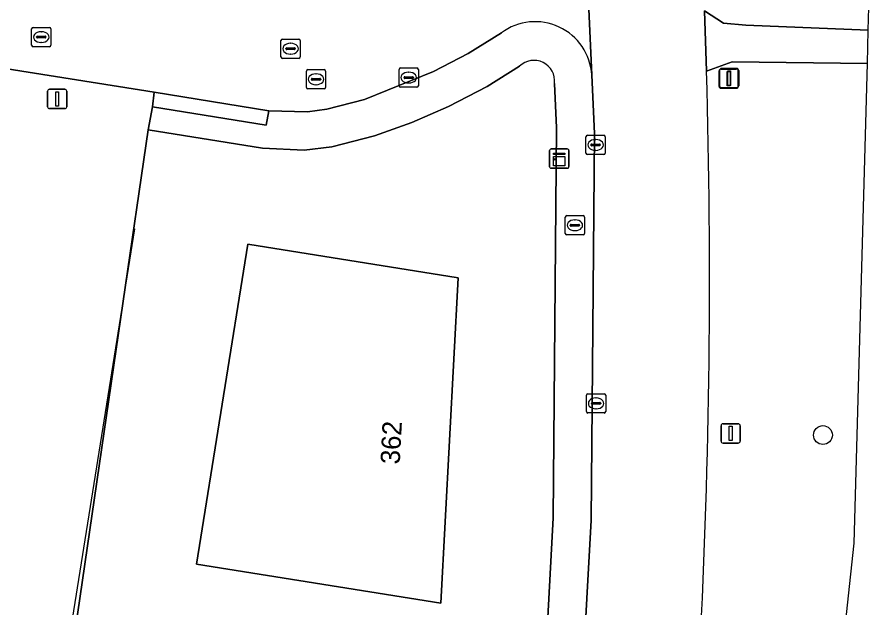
# Model space of a CAD drawing. Extents: x 154324 to 155744, y 382937 to 384188.
# Drawn here: x 155353.31 to 155397.49, y 383349.73 to 383380.36 of the extents above; entities that cross this region are included whole.
import ezdxf

# ---------------------------------------------------------------- set-up
doc = ezdxf.new("R2010")
doc.units = 0
for name, color, linetype in [('IMGEO_Berm_groen', 7, 'Continuous'), ('IMGEO_Boom', 7, 'Continuous'), ('IMGEO_Brandkraan', 7, 'Continuous'), ('IMGEO_Erf', 7, 'Continuous'), ('IMGEO_Groenvoorziening', 7, 'Continuous'), ('IMGEO_Hek', 7, 'Continuous'), ('IMGEO_Kast', 7, 'Continuous'), ('IMGEO_Kolk', 7, 'Continuous'), ('IMGEO_Lichtmast', 7, 'Continuous'), ('IMGEO_Pand', 7, 'Continuous'), ('IMGEO_Pand_nummerreeks', 7, 'Continuous'), ('IMGEO_Rijbaan_lokaal_gesloten', 7, 'Continuous'), ('IMGEO_Rijbaan_lokaal_open', 7, 'Continuous'), ('IMGEO_Rioolput', 7, 'Continuous'), ('IMGEO_Voetpad_halfverhard', 7, 'Continuous'), ('IMGEO_Voetpad_open', 7, 'Continuous')]:
    doc.layers.add(name, color=color, linetype=linetype)

msp = doc.modelspace()

# ---------------------------------------------------------------- linework, layer by layer
at = {"layer": 'IMGEO_Berm_groen'}
for points in [[(155388.962, 383380.68), (155389.952, 383380.04), (155391.104, 383379.937), (155397.46, 383379.674), (155397.493, 383380.862), (155397.072, 383397.736)], [(155393.141, 383320.278), (155393.828, 383326.071), (155396.722, 383353.081), (155397.412, 383377.951), (155390.399, 383378.047), (155389.068, 383377.555)]]:
    msp.add_lwpolyline(points, dxfattribs=at)
msp.add_arc((155026.251, 383366.771), 362.977, 356.94684, 1.70249, dxfattribs=at)
at = {"layer": 'IMGEO_Boom'}
msp.add_circle((155395.106, 383358.693), 0.489, dxfattribs=at)
at = {"layer": 'IMGEO_Brandkraan'}
for p, q in [((155381.741, 383369.142), (155381.741, 383369.994)), ((155381.816, 383370.068), (155382.668, 383370.068)), ((155382.229, 383369.848), (155382.254, 383369.848)), ((155382.742, 383369.994), (155382.742, 383369.142)), ((155382, 383369.562), (155382, 383369.574)), ((155382.438, 383369.525), (155382.04, 383369.525)), ((155382.043, 383369.611), (155382.441, 383369.611)), ((155382.484, 383369.574), (155382.484, 383369.562)), ((155382.668, 383369.068), (155381.816, 383369.068)), ((155382.252, 383369.288), (155382.227, 383369.288))]:
    msp.add_line(p, q, dxfattribs=at)
for points in [[(155381.741, 383369.142), (155381.741, 383369.994)], [(155381.816, 383370.068), (155382.668, 383370.068)], [(155382.742, 383369.994), (155382.742, 383369.142)], [(155382.668, 383369.068), (155381.816, 383369.068)]]:
    msp.add_lwpolyline(points, dxfattribs=at)
for centre, radius, start, end in [((155381.818, 383369.992), 0.0765, 91.552, 178.448), ((155381.818, 383369.992), 0.0765, 91.552, 178.448), ((155382.666, 383369.992), 0.0765, 1.552, 88.448), ((155382.666, 383369.992), 0.0765, 1.552, 88.448), ((155382.04, 383369.571), 0.0403, 85.8775, 175.7526), ((155382.037, 383369.561), 0.0366, 178.938, 274.7102), ((155382.441, 383369.568), 0.043, 264.8664, 352.4533), ((155382.445, 383369.573), 0.0386, 1.7309, 96.639), ((155381.818, 383369.144), 0.0765, 181.552, 268.448), ((155381.818, 383369.144), 0.0765, 181.552, 268.448), ((155382.666, 383369.144), 0.0765, 271.552, 358.448), ((155382.666, 383369.144), 0.0765, 271.552, 358.448)]:
    msp.add_arc(centre, radius, start, end, dxfattribs=at)
for centre, major_axis, ratio, start_param, end_param in [((155382.228, 383369.568), (-0.387, 0.002), 0.722429, 4.712389, 7.853982), ((155382.253, 383369.568), (-0.39, 0.002), 0.717154, 1.570796, 4.712389)]:
    msp.add_ellipse(centre, major_axis=major_axis, ratio=ratio, start_param=start_param, end_param=end_param, dxfattribs=at)
at = {"layer": 'IMGEO_Erf'}
for points in [[(155379.37, 383377.808), (155377.693, 383376.769), (155375.684, 383375.726), (155373.779, 383374.896), (155371.854, 383374.2), (155369.627, 383373.633), (155368.206, 383373.461), (155366.044, 383373.562), (155360.106, 383374.508), (155358.814, 383365.632), (155354.844, 383338.369), (155354.723, 383337.539), (155380.034, 383334.398), (155381.119, 383354.403)], [(155381.119, 383354.403), (155381.295, 383374.612), (155381.184, 383376.925)]]:
    msp.add_lwpolyline(points, dxfattribs=at)
msp.add_lwpolyline([(155362.62, 383351.999), (155365.283, 383368.59), (155376.195, 383366.839), (155375.291, 383349.97)], close=True, dxfattribs=at)
msp.add_arc((155380.121, 383377.046), 1.07, 353.5115, 134.5776, dxfattribs=at)
at = {"layer": 'IMGEO_Groenvoorziening'}
for points in [[(155358.814, 383365.632), (155360.106, 383374.508), (155360.327, 383375.705), (155360.426, 383376.464), (155295.925, 383386.713), (155295.512, 383384.113), (155295.052, 383381.177), (155292.112, 383381.637), (155292.571, 383384.573), (155292.985, 383387.18), (155280.782, 383389.119), (155238.742, 383395.799)], [(155381.974, 383334.287), (155380.034, 383334.398), (155354.723, 383337.539), (155354.844, 383338.369), (155358.814, 383365.632)]]:
    msp.add_lwpolyline(points, dxfattribs=at)
at = {"layer": 'IMGEO_Hek'}
msp.add_lwpolyline([(155369.884, 383336.037), (155354.478, 383338.426), (155359.411, 383369.381)], dxfattribs=at)
at = {"layer": 'IMGEO_Kast'}
for p, q in [((155380.931, 383372.598), (155380.931, 383373.439)), ((155380.931, 383373.439), (155380.931, 383372.598)), ((155381.006, 383373.523), (155381.847, 383373.523)), ((155381.847, 383373.523), (155381.006, 383373.523)), ((155381.931, 383373.448), (155381.931, 383372.607)), ((155381.931, 383372.607), (155381.931, 383373.448)), ((155381.856, 383372.523), (155381.015, 383372.523)), ((155381.015, 383372.523), (155381.856, 383372.523))]:
    msp.add_line(p, q, dxfattribs=at)
for points in [[(155381.126, 383373.313), (155381.726, 383373.313), (155381.726, 383373.228), (155381.126, 383373.228), (155381.126, 383373.313)], [(155381.126, 383373.138), (155381.726, 383373.138), (155381.726, 383372.649), (155381.126, 383372.649), (155381.126, 383373.138)]]:
    msp.add_lwpolyline(points, dxfattribs=at)
msp.add_circle((155381.21, 383372.987), 0.0377, dxfattribs=at)
for centre, start, end in [((155381.009, 383373.445), 92.4484, 184.2845), ((155381.009, 383373.445), 92.4484, 184.2845), ((155381.853, 383373.445), 2.4484, 94.2845), ((155381.853, 383373.445), 2.4484, 94.2845), ((155381.009, 383372.601), 182.4484, 274.2845), ((155381.009, 383372.601), 182.4484, 274.2845), ((155381.853, 383372.601), 272.4484, 4.2845), ((155381.853, 383372.601), 272.4484, 4.2845)]:
    msp.add_arc(centre, 0.0779, start, end, dxfattribs=at)
at = {"layer": 'IMGEO_Kolk'}
for p, q in [((155373.12, 383376.797), (155373.12, 383377.649)), ((155373.195, 383377.723), (155374.047, 383377.723)), ((155373.608, 383377.503), (155373.633, 383377.503)), ((155374.121, 383377.649), (155374.121, 383376.797)), ((155373.379, 383377.217), (155373.379, 383377.229)), ((155373.817, 383377.18), (155373.419, 383377.18)), ((155373.422, 383377.266), (155373.82, 383377.266)), ((155373.631, 383376.943), (155373.606, 383376.943)), ((155373.863, 383377.229), (155373.863, 383377.217)), ((155374.047, 383376.723), (155373.195, 383376.723)), ((155382.815, 383373.305), (155382.815, 383374.157)), ((155382.89, 383374.231), (155383.742, 383374.231)), ((155383.303, 383374.011), (155383.328, 383374.011)), ((155383.816, 383374.157), (155383.816, 383373.305)), ((155383.074, 383373.725), (155383.074, 383373.737)), ((155383.512, 383373.688), (155383.114, 383373.688)), ((155383.117, 383373.774), (155383.515, 383373.774)), ((155383.326, 383373.451), (155383.301, 383373.451)), ((155383.558, 383373.737), (155383.558, 383373.725)), ((155383.742, 383373.231), (155382.89, 383373.231)), ((155382.838, 383359.91), (155382.838, 383360.762)), ((155382.913, 383360.836), (155383.765, 383360.836)), ((155383.326, 383360.616), (155383.351, 383360.616)), ((155383.839, 383360.762), (155383.839, 383359.91)), ((155383.097, 383360.33), (155383.097, 383360.342)), ((155383.535, 383360.293), (155383.137, 383360.293)), ((155383.14, 383360.379), (155383.538, 383360.379)), ((155383.581, 383360.342), (155383.581, 383360.33)), ((155383.765, 383359.836), (155382.913, 383359.836)), ((155383.349, 383360.056), (155383.324, 383360.056))]:
    msp.add_line(p, q, dxfattribs=at)
for points in [[(155373.12, 383376.797), (155373.12, 383377.649)], [(155373.195, 383377.723), (155374.047, 383377.723)], [(155374.121, 383377.649), (155374.121, 383376.797)], [(155374.047, 383376.723), (155373.195, 383376.723)], [(155382.815, 383373.305), (155382.815, 383374.157)], [(155382.89, 383374.231), (155383.742, 383374.231)], [(155383.816, 383374.157), (155383.816, 383373.305)], [(155383.742, 383373.231), (155382.89, 383373.231)], [(155382.838, 383359.91), (155382.838, 383360.762)], [(155382.913, 383360.836), (155383.765, 383360.836)], [(155383.839, 383360.762), (155383.839, 383359.91)], [(155383.765, 383359.836), (155382.913, 383359.836)]]:
    msp.add_lwpolyline(points, dxfattribs=at)
for centre, radius, start, end in [((155373.197, 383377.647), 0.0765, 91.552, 178.448), ((155373.197, 383377.647), 0.0765, 91.552, 178.448), ((155374.045, 383377.647), 0.0765, 1.552, 88.448), ((155374.045, 383377.647), 0.0765, 1.552, 88.448), ((155373.419, 383377.226), 0.0403, 85.8775, 175.7526), ((155373.416, 383377.216), 0.0366, 178.938, 274.7102), ((155373.82, 383377.223), 0.043, 264.8664, 352.4533), ((155373.824, 383377.228), 0.0386, 1.7309, 96.639), ((155373.197, 383376.799), 0.0765, 181.552, 268.448), ((155373.197, 383376.799), 0.0765, 181.552, 268.448), ((155374.045, 383376.799), 0.0765, 271.552, 358.448), ((155374.045, 383376.799), 0.0765, 271.552, 358.448), ((155382.892, 383374.155), 0.0765, 91.552, 178.448), ((155382.892, 383374.155), 0.0765, 91.552, 178.448), ((155383.74, 383374.155), 0.0765, 1.552, 88.448), ((155383.74, 383374.155), 0.0765, 1.552, 88.448), ((155383.114, 383373.734), 0.0403, 85.8775, 175.7526), ((155383.111, 383373.724), 0.0366, 178.938, 274.7102), ((155383.515, 383373.731), 0.043, 264.8664, 352.4533), ((155383.519, 383373.736), 0.0386, 1.7309, 96.639), ((155382.892, 383373.307), 0.0765, 181.552, 268.448), ((155382.892, 383373.307), 0.0765, 181.552, 268.448), ((155383.74, 383373.307), 0.0765, 271.552, 358.448), ((155383.74, 383373.307), 0.0765, 271.552, 358.448), ((155382.915, 383360.76), 0.0765, 91.552, 178.448), ((155382.915, 383360.76), 0.0765, 91.552, 178.448), ((155383.763, 383360.76), 0.0765, 1.552, 88.448), ((155383.763, 383360.76), 0.0765, 1.552, 88.448), ((155383.137, 383360.339), 0.0403, 85.8775, 175.7526), ((155383.134, 383360.329), 0.0366, 178.938, 274.7102), ((155383.538, 383360.336), 0.043, 264.8664, 352.4533), ((155383.542, 383360.341), 0.0386, 1.7309, 96.639), ((155382.915, 383359.912), 0.0765, 181.552, 268.448), ((155382.915, 383359.912), 0.0765, 181.552, 268.448), ((155383.763, 383359.912), 0.0765, 271.552, 358.448), ((155383.763, 383359.912), 0.0765, 271.552, 358.448)]:
    msp.add_arc(centre, radius, start, end, dxfattribs=at)
for centre, major_axis, ratio, start_param, end_param in [((155373.607, 383377.223), (-0.387, 0.002), 0.722429, 4.712389, 7.853982), ((155373.632, 383377.223), (-0.39, 0.002), 0.717154, 1.570796, 4.712389), ((155383.302, 383373.731), (-0.387, 0.002), 0.722429, 4.712389, 7.853982), ((155383.327, 383373.731), (-0.39, 0.002), 0.717154, 1.570796, 4.712389), ((155383.325, 383360.336), (-0.387, 0.002), 0.722429, 4.712389, 7.853982), ((155383.35, 383360.336), (-0.39, 0.002), 0.717154, 1.570796, 4.712389)]:
    msp.add_ellipse(centre, major_axis=major_axis, ratio=ratio, start_param=start_param, end_param=end_param, dxfattribs=at)
at = {"layer": 'IMGEO_Lichtmast'}
for p, q in [((155389.723, 383376.768), (155389.723, 383377.568)), ((155389.723, 383377.568), (155389.723, 383376.768)), ((155389.747, 383376.795), (155389.747, 383377.595)), ((155389.747, 383377.595), (155389.747, 383376.795)), ((155389.823, 383377.668), (155390.613, 383377.668)), ((155390.613, 383377.668), (155389.823, 383377.668)), ((155389.847, 383377.695), (155390.637, 383377.695)), ((155390.637, 383377.695), (155389.847, 383377.695)), ((155390.713, 383377.568), (155390.713, 383376.768)), ((155390.713, 383376.768), (155390.713, 383377.568)), ((155390.737, 383377.595), (155390.737, 383376.795)), ((155390.737, 383376.795), (155390.737, 383377.595)), ((155354.892, 383375.716), (155354.892, 383376.516)), ((155354.892, 383376.516), (155354.892, 383375.716)), ((155354.992, 383376.616), (155355.782, 383376.616)), ((155355.782, 383376.616), (155354.992, 383376.616)), ((155355.882, 383376.516), (155355.882, 383375.716)), ((155355.882, 383375.716), (155355.882, 383376.516)), ((155390.613, 383376.668), (155389.823, 383376.668)), ((155389.823, 383376.668), (155390.613, 383376.668)), ((155390.637, 383376.695), (155389.847, 383376.695)), ((155389.847, 383376.695), (155390.637, 383376.695)), ((155355.782, 383375.616), (155354.992, 383375.616)), ((155354.992, 383375.616), (155355.782, 383375.616)), ((155389.923, 383359.277), (155390.713, 383359.277)), ((155390.713, 383359.277), (155389.923, 383359.277)), ((155389.823, 383358.377), (155389.823, 383359.177)), ((155389.823, 383359.177), (155389.823, 383358.377)), ((155390.813, 383359.177), (155390.813, 383358.377)), ((155390.813, 383358.377), (155390.813, 383359.177)), ((155390.713, 383358.277), (155389.923, 383358.277)), ((155389.923, 383358.277), (155390.713, 383358.277))]:
    msp.add_line(p, q, dxfattribs=at)
for points in [[(155390.143, 383377.543), (155390.293, 383377.543), (155390.293, 383376.793), (155390.143, 383376.793), (155390.143, 383377.543)], [(155390.167, 383377.57), (155390.317, 383377.57), (155390.317, 383376.82), (155390.167, 383376.82), (155390.167, 383377.57)], [(155355.312, 383376.491), (155355.462, 383376.491), (155355.462, 383375.741), (155355.312, 383375.741), (155355.312, 383376.491)], [(155390.243, 383359.152), (155390.393, 383359.152), (155390.393, 383358.402), (155390.243, 383358.402), (155390.243, 383359.152)]]:
    msp.add_lwpolyline(points, dxfattribs=at)
for centre, start, end in [((155389.823, 383377.568), 90, 180), ((155389.823, 383377.568), 90, 180), ((155389.847, 383377.595), 90, 180), ((155389.847, 383377.595), 90, 180), ((155390.613, 383377.568), 0, 90), ((155390.613, 383377.568), 360, 90), ((155390.637, 383377.595), 0, 90), ((155390.637, 383377.595), 360, 90), ((155354.992, 383376.516), 90, 180), ((155354.992, 383376.516), 90, 180), ((155355.782, 383376.516), 0, 90), ((155355.782, 383376.516), 360, 90), ((155389.823, 383376.768), 180, 270), ((155389.823, 383376.768), 180, 270), ((155389.847, 383376.795), 180, 270), ((155389.847, 383376.795), 180, 270), ((155390.613, 383376.768), 270, 0), ((155390.613, 383376.768), 270, 0), ((155390.637, 383376.795), 270, 0), ((155390.637, 383376.795), 270, 0), ((155354.992, 383375.716), 180, 270), ((155354.992, 383375.716), 180, 270), ((155355.782, 383375.716), 270, 0), ((155355.782, 383375.716), 270, 0), ((155389.923, 383359.177), 90, 180), ((155389.923, 383359.177), 90, 180), ((155390.713, 383359.177), 0, 90), ((155390.713, 383359.177), 360, 90), ((155389.923, 383358.377), 180, 270), ((155389.923, 383358.377), 180, 270), ((155390.713, 383358.377), 270, 0), ((155390.713, 383358.377), 270, 0)]:
    msp.add_arc(centre, 0.1, start, end, dxfattribs=at)
at = {"layer": 'IMGEO_Pand'}
msp.add_lwpolyline([(155376.195, 383366.839), (155365.283, 383368.59), (155362.62, 383351.999), (155375.291, 383349.97)], close=True, dxfattribs=at)
at = {"layer": 'IMGEO_Rijbaan_lokaal_gesloten'}
for points in [[(155383.12, 383377.352), (155382.189, 383397.912)], [(155238.742, 383395.799), (155280.782, 383389.119), (155292.985, 383387.18), (155295.925, 383386.713), (155360.426, 383376.464), (155366.366, 383375.502), (155368.377, 383375.447), (155369.374, 383375.593), (155371.331, 383376.087), (155374.899, 383377.537), (155376.703, 383378.478), (155378.429, 383379.542)]]:
    msp.add_lwpolyline(points, dxfattribs=at)
msp.add_arc((155380.182, 383377.178), 2.943, 3.3838, 126.5651, dxfattribs=at)
at = {"layer": 'IMGEO_Rijbaan_lokaal_open'}
for points in [[(155379.61, 383421.518), (155379.69, 383421.052), (155380.297, 383417.532), (155380.555, 383416.035), (155380.615, 383415.683), (155382.189, 383397.912), (155383.12, 383377.352), (155383.264, 383374.318), (155383.19, 383366.215), (155383.081, 383354.275), (155381.974, 383334.287)], [(155389.068, 383377.555), (155388.962, 383380.68)]]:
    msp.add_lwpolyline(points, dxfattribs=at)
msp.add_arc((155026.251, 383366.771), 362.977, 356.94684, 1.70249, dxfattribs=at)
at = {"layer": 'IMGEO_Rioolput'}
for p, q in [((155354.064, 383378.898), (155354.064, 383379.75)), ((155354.139, 383379.824), (155354.991, 383379.824)), ((155354.552, 383379.604), (155354.577, 383379.604)), ((155355.065, 383379.75), (155355.065, 383378.898)), ((155354.323, 383379.318), (155354.323, 383379.33)), ((155354.761, 383379.281), (155354.363, 383379.281)), ((155354.366, 383379.367), (155354.764, 383379.367)), ((155354.807, 383379.33), (155354.807, 383379.318)), ((155366.996, 383378.295), (155366.996, 383379.147)), ((155367.071, 383379.221), (155367.923, 383379.221)), ((155367.997, 383379.147), (155367.997, 383378.295)), ((155354.991, 383378.824), (155354.139, 383378.824)), ((155354.575, 383379.044), (155354.55, 383379.044)), ((155367.255, 383378.715), (155367.255, 383378.727)), ((155367.693, 383378.678), (155367.295, 383378.678)), ((155367.298, 383378.764), (155367.696, 383378.764)), ((155367.484, 383379.001), (155367.509, 383379.001)), ((155367.739, 383378.727), (155367.739, 383378.715)), ((155367.507, 383378.441), (155367.482, 383378.441)), ((155367.923, 383378.221), (155367.071, 383378.221)), ((155368.313, 383376.71), (155368.313, 383377.562)), ((155368.388, 383377.636), (155369.24, 383377.636)), ((155368.801, 383377.416), (155368.826, 383377.416)), ((155369.314, 383377.562), (155369.314, 383376.71)), ((155368.572, 383377.13), (155368.572, 383377.142)), ((155369.01, 383377.093), (155368.612, 383377.093)), ((155368.615, 383377.179), (155369.013, 383377.179)), ((155369.056, 383377.142), (155369.056, 383377.13)), ((155369.24, 383376.636), (155368.388, 383376.636)), ((155368.824, 383376.856), (155368.799, 383376.856))]:
    msp.add_line(p, q, dxfattribs=at)
for points in [[(155354.064, 383378.898), (155354.064, 383379.75)], [(155354.139, 383379.824), (155354.991, 383379.824)], [(155355.065, 383379.75), (155355.065, 383378.898)], [(155366.996, 383378.295), (155366.996, 383379.147)], [(155367.071, 383379.221), (155367.923, 383379.221)], [(155367.997, 383379.147), (155367.997, 383378.295)], [(155354.991, 383378.824), (155354.139, 383378.824)], [(155367.923, 383378.221), (155367.071, 383378.221)], [(155368.313, 383376.71), (155368.313, 383377.562)], [(155368.388, 383377.636), (155369.24, 383377.636)], [(155369.314, 383377.562), (155369.314, 383376.71)], [(155369.24, 383376.636), (155368.388, 383376.636)]]:
    msp.add_lwpolyline(points, dxfattribs=at)
for centre, radius, start, end in [((155354.141, 383379.748), 0.0765, 91.552, 178.448), ((155354.141, 383379.748), 0.0765, 91.552, 178.448), ((155354.989, 383379.748), 0.0765, 1.552, 88.448), ((155354.989, 383379.748), 0.0765, 1.552, 88.448), ((155354.363, 383379.327), 0.0403, 85.8775, 175.7526), ((155354.36, 383379.317), 0.0366, 178.938, 274.7102), ((155354.764, 383379.324), 0.043, 264.8664, 352.4533), ((155354.768, 383379.329), 0.0386, 1.7309, 96.639), ((155367.073, 383379.145), 0.0765, 91.552, 178.448), ((155367.073, 383379.145), 0.0765, 91.552, 178.448), ((155367.921, 383379.145), 0.0765, 1.552, 88.448), ((155367.921, 383379.145), 0.0765, 1.552, 88.448), ((155354.141, 383378.9), 0.0765, 181.552, 268.448), ((155354.141, 383378.9), 0.0765, 181.552, 268.448), ((155354.989, 383378.9), 0.0765, 271.552, 358.448), ((155354.989, 383378.9), 0.0765, 271.552, 358.448), ((155367.295, 383378.724), 0.0403, 85.8775, 175.7526), ((155367.292, 383378.714), 0.0366, 178.938, 274.7102), ((155367.696, 383378.721), 0.043, 264.8664, 352.4533), ((155367.7, 383378.726), 0.0386, 1.7309, 96.639), ((155367.073, 383378.297), 0.0765, 181.552, 268.448), ((155367.073, 383378.297), 0.0765, 181.552, 268.448), ((155367.921, 383378.297), 0.0765, 271.552, 358.448), ((155367.921, 383378.297), 0.0765, 271.552, 358.448), ((155368.39, 383377.56), 0.0765, 91.552, 178.448), ((155368.39, 383377.56), 0.0765, 91.552, 178.448), ((155369.238, 383377.56), 0.0765, 1.552, 88.448), ((155369.238, 383377.56), 0.0765, 1.552, 88.448), ((155368.612, 383377.139), 0.0403, 85.8775, 175.7526), ((155368.609, 383377.129), 0.0366, 178.938, 274.7102), ((155369.013, 383377.136), 0.043, 264.8664, 352.4533), ((155369.017, 383377.141), 0.0386, 1.7309, 96.639), ((155368.39, 383376.712), 0.0765, 181.552, 268.448), ((155368.39, 383376.712), 0.0765, 181.552, 268.448), ((155369.238, 383376.712), 0.0765, 271.552, 358.448), ((155369.238, 383376.712), 0.0765, 271.552, 358.448)]:
    msp.add_arc(centre, radius, start, end, dxfattribs=at)
for centre, major_axis, ratio, start_param, end_param in [((155354.551, 383379.324), (-0.387, 0.002), 0.722429, 4.712389, 7.853982), ((155354.576, 383379.324), (-0.39, 0.002), 0.717154, 1.570796, 4.712389), ((155367.483, 383378.721), (-0.387, 0.002), 0.722429, 4.712389, 7.853982), ((155367.508, 383378.721), (-0.39, 0.002), 0.717154, 1.570796, 4.712389), ((155368.8, 383377.136), (-0.387, 0.002), 0.722429, 4.712389, 7.853982), ((155368.825, 383377.136), (-0.39, 0.002), 0.717154, 1.570796, 4.712389)]:
    msp.add_ellipse(centre, major_axis=major_axis, ratio=ratio, start_param=start_param, end_param=end_param, dxfattribs=at)
at = {"layer": 'IMGEO_Voetpad_halfverhard'}
msp.add_lwpolyline([(155397.412, 383377.951), (155397.46, 383379.674), (155391.104, 383379.937), (155389.952, 383380.04), (155388.962, 383380.68), (155389.068, 383377.555), (155390.399, 383378.047)], close=True, dxfattribs=at)
at = {"layer": 'IMGEO_Voetpad_open'}
for points in [[(155378.429, 383379.542), (155376.703, 383378.478), (155374.899, 383377.537), (155371.331, 383376.087), (155369.374, 383375.593), (155368.377, 383375.447), (155366.366, 383375.502), (155366.231, 383374.76), (155360.327, 383375.705), (155360.106, 383374.508), (155366.044, 383373.562), (155368.206, 383373.461), (155369.627, 383373.633), (155371.854, 383374.2), (155373.779, 383374.896), (155375.684, 383375.726), (155377.693, 383376.769), (155379.37, 383377.808)], [(155381.184, 383376.925), (155381.295, 383374.612), (155381.119, 383354.403), (155380.034, 383334.398), (155381.974, 383334.287), (155383.081, 383354.275), (155383.19, 383366.215), (155383.264, 383374.318), (155383.12, 383377.352)]]:
    msp.add_lwpolyline(points, dxfattribs=at)
msp.add_lwpolyline([(155360.327, 383375.705), (155366.231, 383374.76), (155366.366, 383375.502), (155360.426, 383376.464)], close=True, dxfattribs=at)
for centre, radius, start, end in [((155380.182, 383377.178), 2.943, 3.3838, 126.5651), ((155380.121, 383377.046), 1.07, 353.5115, 134.5776)]:
    msp.add_arc(centre, radius, start, end, dxfattribs=at)

# ---------------------------------------------------------------- texts
at = {"layer": 'IMGEO_Pand_nummerreeks'}
msp.add_text('362', height=1, rotation=86.9313, dxfattribs=at).set_placement((155373.153, 383357.159))

doc.saveas('drawing.dxf')
